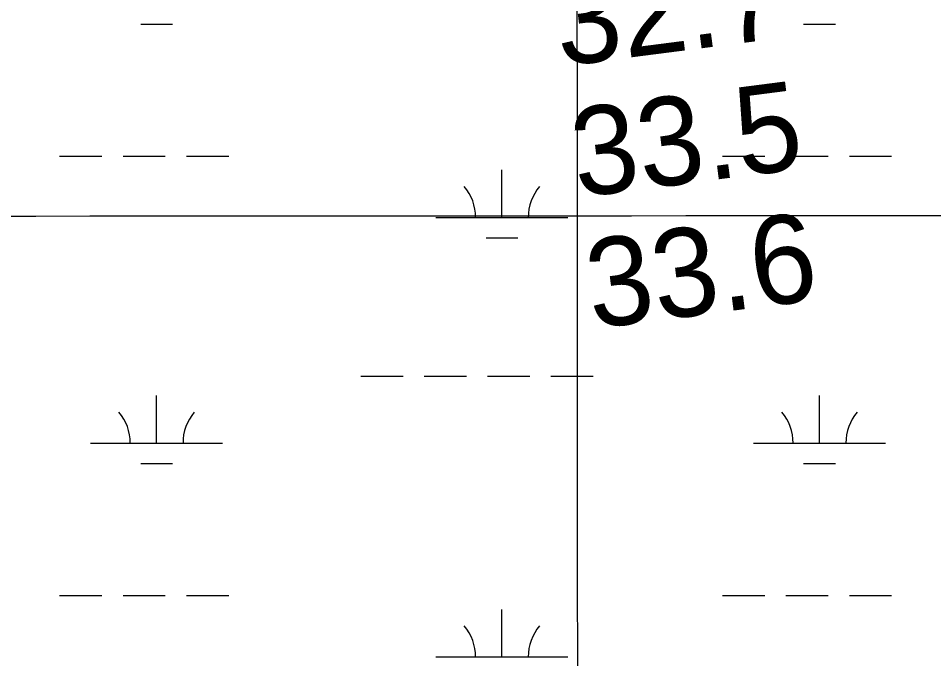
# Model space of a CAD drawing. Extents: x 3281947 to 3319794, y 715894 to 741249.
# Drawn here: x 3301406 to 3302099, y 727003 to 727488 of the extents above; entities that cross this region are included whole.
import ezdxf

# ---------------------------------------------------------------- set-up
doc = ezdxf.new("R2010")
doc.units = 0
for name, color, linetype in [('V-GRID-MAJR', 7, 'Continuous'), ('V-RIVR-RANG', 7, 'Continuous'), ('V-WETL-SWMP', 7, 'Continuous')]:
    doc.layers.add(name, color=color, linetype=linetype)

msp = doc.modelspace()

# ---------------------------------------------------------------- linework, layer by layer
at = {"layer": 'V-GRID-MAJR'}
for points in [[(3301833.19, 721280.147), (3301829.665, 727338.411), (3301826.139, 733400.14), (3301822.612, 739461.902), (3301822.61, 739465.335)], [(3286082.416, 727332.685), (3291331.5, 727333.83), (3296580.583, 727335.738), (3301829.665, 727338.411), (3307078.748, 727341.846), (3312327.829, 727346.045), (3317576.91, 727351.008), (3317576.911, 727351.008)]]:
    msp.add_spline(points, degree=3, dxfattribs=at)
at = {"layer": 'V-WETL-SWMP'}
for p, q in [((3301499.0380903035, 727483.4912456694), (3301523.038090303, 727483.4912456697)), ((3302000.9460903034, 727483.4912456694), (3302024.946090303, 727483.4912456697)), ((3301437.6300903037, 727383.4902456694), (3301469.6300903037, 727383.4902456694)), ((3301485.6300903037, 727383.4902456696), (3301517.6300903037, 727383.4902456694)), ((3301533.6300903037, 727383.4902456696), (3301565.6300903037, 727383.4902456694)), ((3301939.5380903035, 727383.4902456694), (3301971.5380903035, 727383.4902456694)), ((3301987.5380903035, 727383.4902456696), (3302019.5380903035, 727383.4902456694)), ((3302035.5380903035, 727383.4902456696), (3302067.5380903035, 727383.4902456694)), ((3301772.4740903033, 727337.0602456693), (3301772.4740903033, 727373.0602456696)), ((3301722.4740903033, 727337.0602456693), (3301822.4740903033, 727337.0602456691)), ((3301760.4740903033, 727321.6292456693), (3301784.474090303, 727321.6292456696)), ((3301665.6300903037, 727216.9892456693), (3301697.6300903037, 727216.9892456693)), ((3301713.6300903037, 727216.9892456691), (3301745.6300903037, 727216.9892456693)), ((3301761.6300903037, 727216.9892456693), (3301793.6300903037, 727216.9892456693)), ((3301809.6300903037, 727216.9892456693), (3301841.6300903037, 727216.9892456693)), ((3301511.0380903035, 727166.2472456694), (3301511.0380903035, 727202.2472456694)), ((3302012.9460903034, 727166.2472456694), (3302012.9460903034, 727202.2472456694)), ((3301461.0380903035, 727166.2472456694), (3301561.0380903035, 727166.2472456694)), ((3301962.9460903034, 727166.2472456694), (3302062.9460903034, 727166.2472456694)), ((3301499.0380903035, 727150.8162456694), (3301523.038090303, 727150.8162456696)), ((3302000.9460903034, 727150.8162456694), (3302024.946090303, 727150.8162456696)), ((3301437.6300903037, 727050.8152456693), (3301469.6300903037, 727050.8152456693)), ((3301485.6300903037, 727050.8152456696), (3301517.6300903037, 727050.8152456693)), ((3301533.6300903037, 727050.8152456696), (3301565.6300903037, 727050.8152456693)), ((3301939.5380903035, 727050.8152456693), (3301971.5380903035, 727050.8152456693)), ((3301987.5380903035, 727050.8152456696), (3302019.5380903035, 727050.8152456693)), ((3302035.5380903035, 727050.8152456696), (3302067.5380903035, 727050.8152456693)), ((3301772.4740903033, 727004.3852456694), (3301772.4740903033, 727040.3852456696)), ((3301722.4740903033, 727004.3852456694), (3301822.4740903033, 727004.3852456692))]:
    msp.add_line(p, q, dxfattribs=at)
for centre, radius, start, end in [((3301717.2311542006, 727337.5350488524), 35.24628790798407, 359.2281799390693, 40.771838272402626), ((3301827.7170264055, 727337.5350488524), 35.246287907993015, 139.2281769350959, 180.77183526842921), ((3301455.7951542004, 727166.7220488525), 35.24628790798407, 359.2281799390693, 40.771838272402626), ((3301566.2810264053, 727166.7220488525), 35.246287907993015, 139.2281769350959, 180.77183526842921), ((3301957.7031542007, 727166.7220488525), 35.24628790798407, 359.2281799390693, 40.771838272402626), ((3302068.1890264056, 727166.7220488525), 35.246287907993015, 139.2281769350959, 180.77183526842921), ((3301717.2311542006, 727004.8600488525), 35.24628790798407, 359.2281799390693, 40.771838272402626), ((3301827.7170264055, 727004.8600488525), 35.246287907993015, 139.2281769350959, 180.77183526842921)]:
    msp.add_arc(centre, radius, start, end, dxfattribs=at)

# ---------------------------------------------------------------- texts
at = {"layer": 'V-RIVR-RANG'}
for s, p in [('32.7', (3301816.701801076, 727451.3481687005)), ('33.5', (3301829.731801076, 727352.2011687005)), ('33.6', (3301840.9305094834, 727252.8170047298))]:
    msp.add_text(s, height=66.99999999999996, rotation=7.348325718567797, dxfattribs=at).set_placement(p)

doc.saveas('drawing.dxf')
